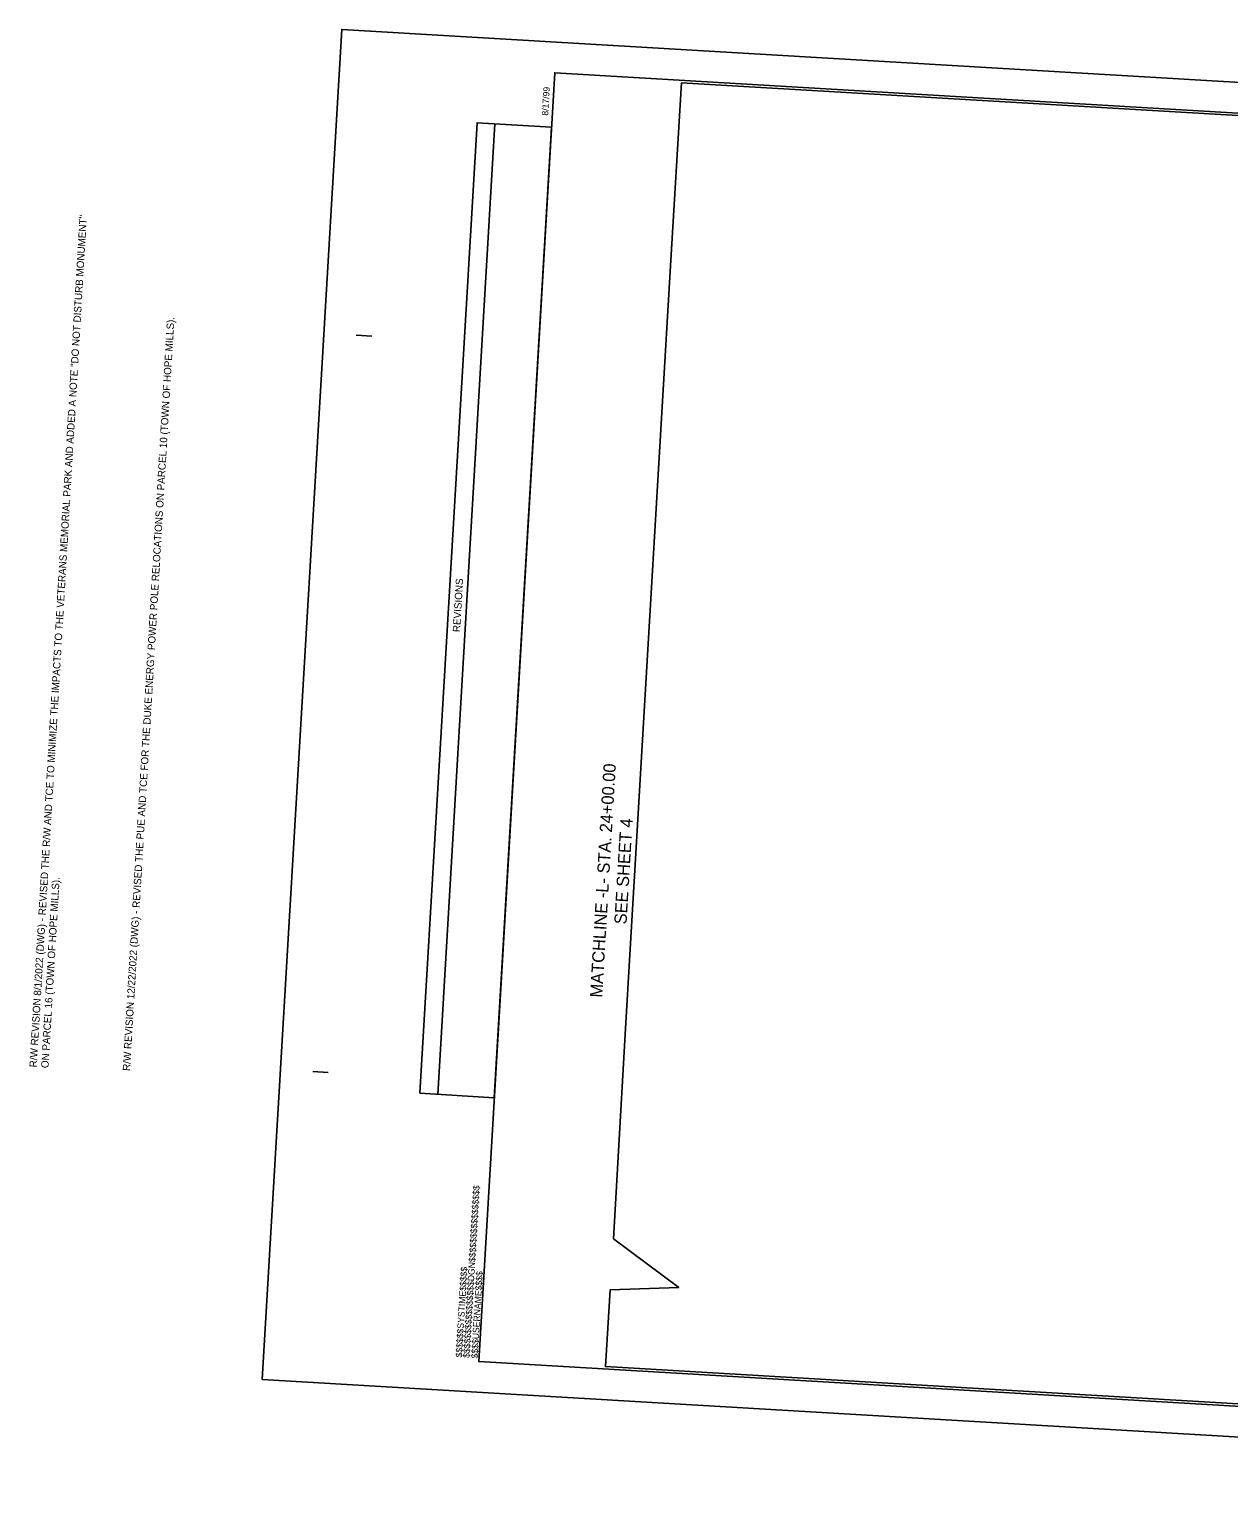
# Model space of a CAD drawing. Extents: x 2012145 to 2014096, y 444445 to 445643.
# Drawn here: x 2012145 to 2013121, y 444445 to 445643 of the extents above; entities that cross this region are included whole.
import ezdxf

# ---------------------------------------------------------------- set-up
doc = ezdxf.new("R2010")
doc.units = 0
for name, color, linetype in [('Matchline', 7, 'Continuous'), ('Matchline Text', 7, 'Continuous'), ('Old_Level_1', 7, 'Continuous'), ('Sheet Block Revision CELL', 7, 'Continuous'), ('Sheet Block System Information CELL', 7, 'Continuous'), ('Sheet Clip Boundary CELL', 7, 'Continuous'), ('Sheet Plan And Profile CELL', 7, 'Continuous'), ('Sheet Plot Border Outside CELL', 7, 'Continuous')]:
    doc.layers.add(name, color=color, linetype=linetype)

msp = doc.modelspace()

# ---------------------------------------------------------------- linework, layer by layer
at = {"layer": 'Matchline'}
msp.add_line((2012629.9, 444830.5), (2012644, 445070), dxfattribs=at)
at = {"layer": 'Sheet Block Revision CELL'}
msp.add_line((2012477.2, 444777), (2012523.7, 445566.3), dxfattribs=at)
msp.add_lwpolyline([(2012462.7, 444777.9), (2012509.2, 445567.2), (2012569.7, 445563.6), (2012523.1, 444774.3)], close=True, dxfattribs=at)
at = {"layer": 'Sheet Block System Information CELL'}
msp.add_line((2012510.5, 444559.7), (2012510.5, 444559.7), dxfattribs=at)
at = {"layer": 'Sheet Clip Boundary CELL'}
msp.add_lwpolyline([(2013668.2, 445541.3), (2012675.5, 445599.8), (2012666.5, 445450.9), (2012644, 445070), (2012629.9, 444830.5), (2012620, 444659.5), (2012673.2, 444619.9), (2012617.3, 444618), (2012613.7, 444555.6), (2014006, 444473.5), (2014042, 445083.4), (2013915.8, 445258.4), (2013612.4, 445329.9), (2013616, 445390.9), (2013652.4, 445436.9), (2013664.2, 445474.7)], close=True, dxfattribs=at)
at = {"layer": 'Sheet Plan And Profile CELL'}
for p, q in [((2012410.9, 445394.5), (2012423.4, 445393.8)), ((2012375.6, 444795.5), (2012388.1, 444794.8)), ((2012510.5, 444559.7), (2012510.5, 444559.7)), ((2012510.5, 444559.7), (2012510.5, 444559.7)), ((2012510.5, 444559.7), (2012510.5, 444559.7)), ((2012510.5, 444559.7), (2012510.5, 444559.7)), ((2012510.5, 444559.7), (2012510.5, 444559.7))]:
    msp.add_line(p, q, dxfattribs=at)
msp.add_lwpolyline([(2014069.7, 445519.6), (2012572.3, 445607.9), (2012510.5, 444559.7), (2014007.9, 444471.4)], close=True, dxfattribs=at)
at = {"layer": 'Sheet Plot Border Outside CELL'}
msp.add_lwpolyline([(2012334.3, 444545), (2014031.4, 444445), (2014096.1, 445543.1), (2012399, 445643.1)], close=True, dxfattribs=at)

# ---------------------------------------------------------------- texts
at = {"layer": 'Matchline Text'}
for s, p in [('MATCHLINE -L- STA. 24+00.00', (2012610.9, 444855.5)), ('SEE SHEET 4', (2012630.7, 444915.1))]:
    msp.add_text(s, height=10, rotation=86.6264, dxfattribs=at).set_placement(p)
at = {"layer": 'Old_Level_1'}
for s, p in [('R/W REVISION 8/1/2022 (DWG) - REVISED THE R/W AND TCE TO MINIMIZE THE IMPACTS TO THE VETERANS MEMORIAL PARK AND ADDED A NOTE "DO NOT DISTURB MONUMENT" ', (2012150.9, 444798.8)), ('R/W REVISION 12/22/2022 (DWG) - REVISED THE PUE AND TCE FOR THE DUKE ENERGY POWER POLE RELOCATIONS ON PARCEL 10 (TOWN OF HOPE MILLS).', (2012226.8, 444795.9)), ('ON PARCEL 16 (TOWN OF HOPE MILLS).', (2012160.4, 444798.2))]:
    msp.add_text(s, height=6, rotation=86.6264, dxfattribs=at).set_placement(p)
at = {"layer": 'Sheet Block Revision CELL'}
msp.add_text('REVISIONS', height=6, rotation=86.6264, dxfattribs=at).set_placement((2012495.3, 445152.8))
at = {"layer": 'Sheet Block System Information CELL'}
for s, p in [('$$$$$$$$$$$$$$$$DGN$$$$$$$$$$$$$$$$', (2012503, 444562.5)), ('$$$$$$SYSTIME$$$$$', (2012496.9, 444562.9)), ('$$$$USERNAME$$$$', (2012509.6, 444562.1))]:
    msp.add_text(s, height=5.25, rotation=86.6264, dxfattribs=at).set_placement(p)
at = {"layer": 'Sheet Plan And Profile CELL'}
msp.add_text('8/17/99', height=5.25, rotation=86.6264, dxfattribs=at).set_placement((2012567, 445572.9))

doc.saveas('drawing.dxf')
